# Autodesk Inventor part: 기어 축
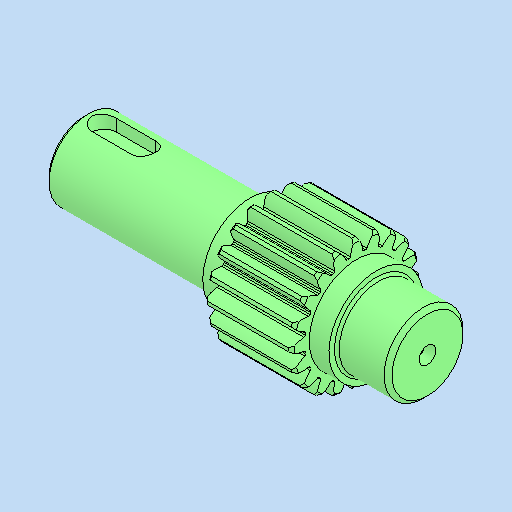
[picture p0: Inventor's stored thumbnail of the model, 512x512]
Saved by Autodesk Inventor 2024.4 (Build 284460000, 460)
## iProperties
Created: 2025-11
Part Number: 기어 축
Material: 강철, 합금
Document SubType Name: Modeling
Designer: home
Density: 7.73 g/cm^3
Appearance: 기본값
Author: jhkim
Sending System: Autodesk Inventor 2026
Preprocessor: ST-DEVELOPER v20.1
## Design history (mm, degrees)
feature "솔리드1"
node "솔리드2"
